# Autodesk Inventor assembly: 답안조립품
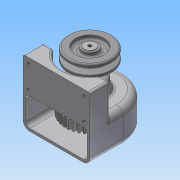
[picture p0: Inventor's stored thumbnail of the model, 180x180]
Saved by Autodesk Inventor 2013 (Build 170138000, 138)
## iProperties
Created: 2015-02
Part Number: 답안조립품
Document SubType Name: Assembly
Designer: Administrator
Author: Administrator
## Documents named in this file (12)
- C:\Documents and Settings\Administrator\바탕 화면\450214V1029\답안조립품.iam
- C:\Documents and Settings\Administrator\바탕 화면\450214V1029\1-본체.ipt
- C:\Documents and Settings\Administrator\바탕 화면\450214V1029\베어링 6001.ipt
- C:\Documents and Settings\Administrator\바탕 화면\450214V1029\축.ipt
- C:\Documents and Settings\Administrator\바탕 화면\450214V1029\키5x5.ipt
- C:\Documents and Settings\Administrator\바탕 화면\450214V1029\5-스퍼기어.ipt
- C:\Documents and Settings\Administrator\바탕 화면\450214V1029\축커버.ipt
- C:\Documents and Settings\Administrator\바탕 화면\450214V1029\M3x0.5.ipt
- C:\Documents and Settings\Administrator\바탕 화면\450214V1029\4-v-벨트풀리.ipt
- C:\Documents and Settings\Administrator\바탕 화면\450214V1029\와샤.ipt
- C:\Documents and Settings\Administrator\바탕 화면\450214V1029\키4x4.ipt
- C:\Documents and Settings\Administrator\바탕 화면\450214V1029\오일실.ipt
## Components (6 placed, 3 different names)
1. 1-본체:1
2. 4-v-벨트풀리:1 — 각도:4
3. M3x0.5:1
4. M3x0.5:2
5. M3x0.5:3
6. M3x0.5:4
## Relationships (1: Angle 1)
- 각도:4 [Angle]: 4-v-벨트풀리:1
